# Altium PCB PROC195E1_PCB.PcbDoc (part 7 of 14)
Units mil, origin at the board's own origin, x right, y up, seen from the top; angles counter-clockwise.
Board outline 3110.24 x 2500 mil, 10 copper layers (Top Layer, L02_GND1, L03_SIG1, L04_GND2, L05_PWR1, L06_PWR2, L07_GND3, L08_SIG2, L09_GND4, Bottom Layer), stack 66.407 mil thick; 571 components, 538 nets, 6726 pads, 1286 vias.
Unrouted connection lines stored in the file: 4.
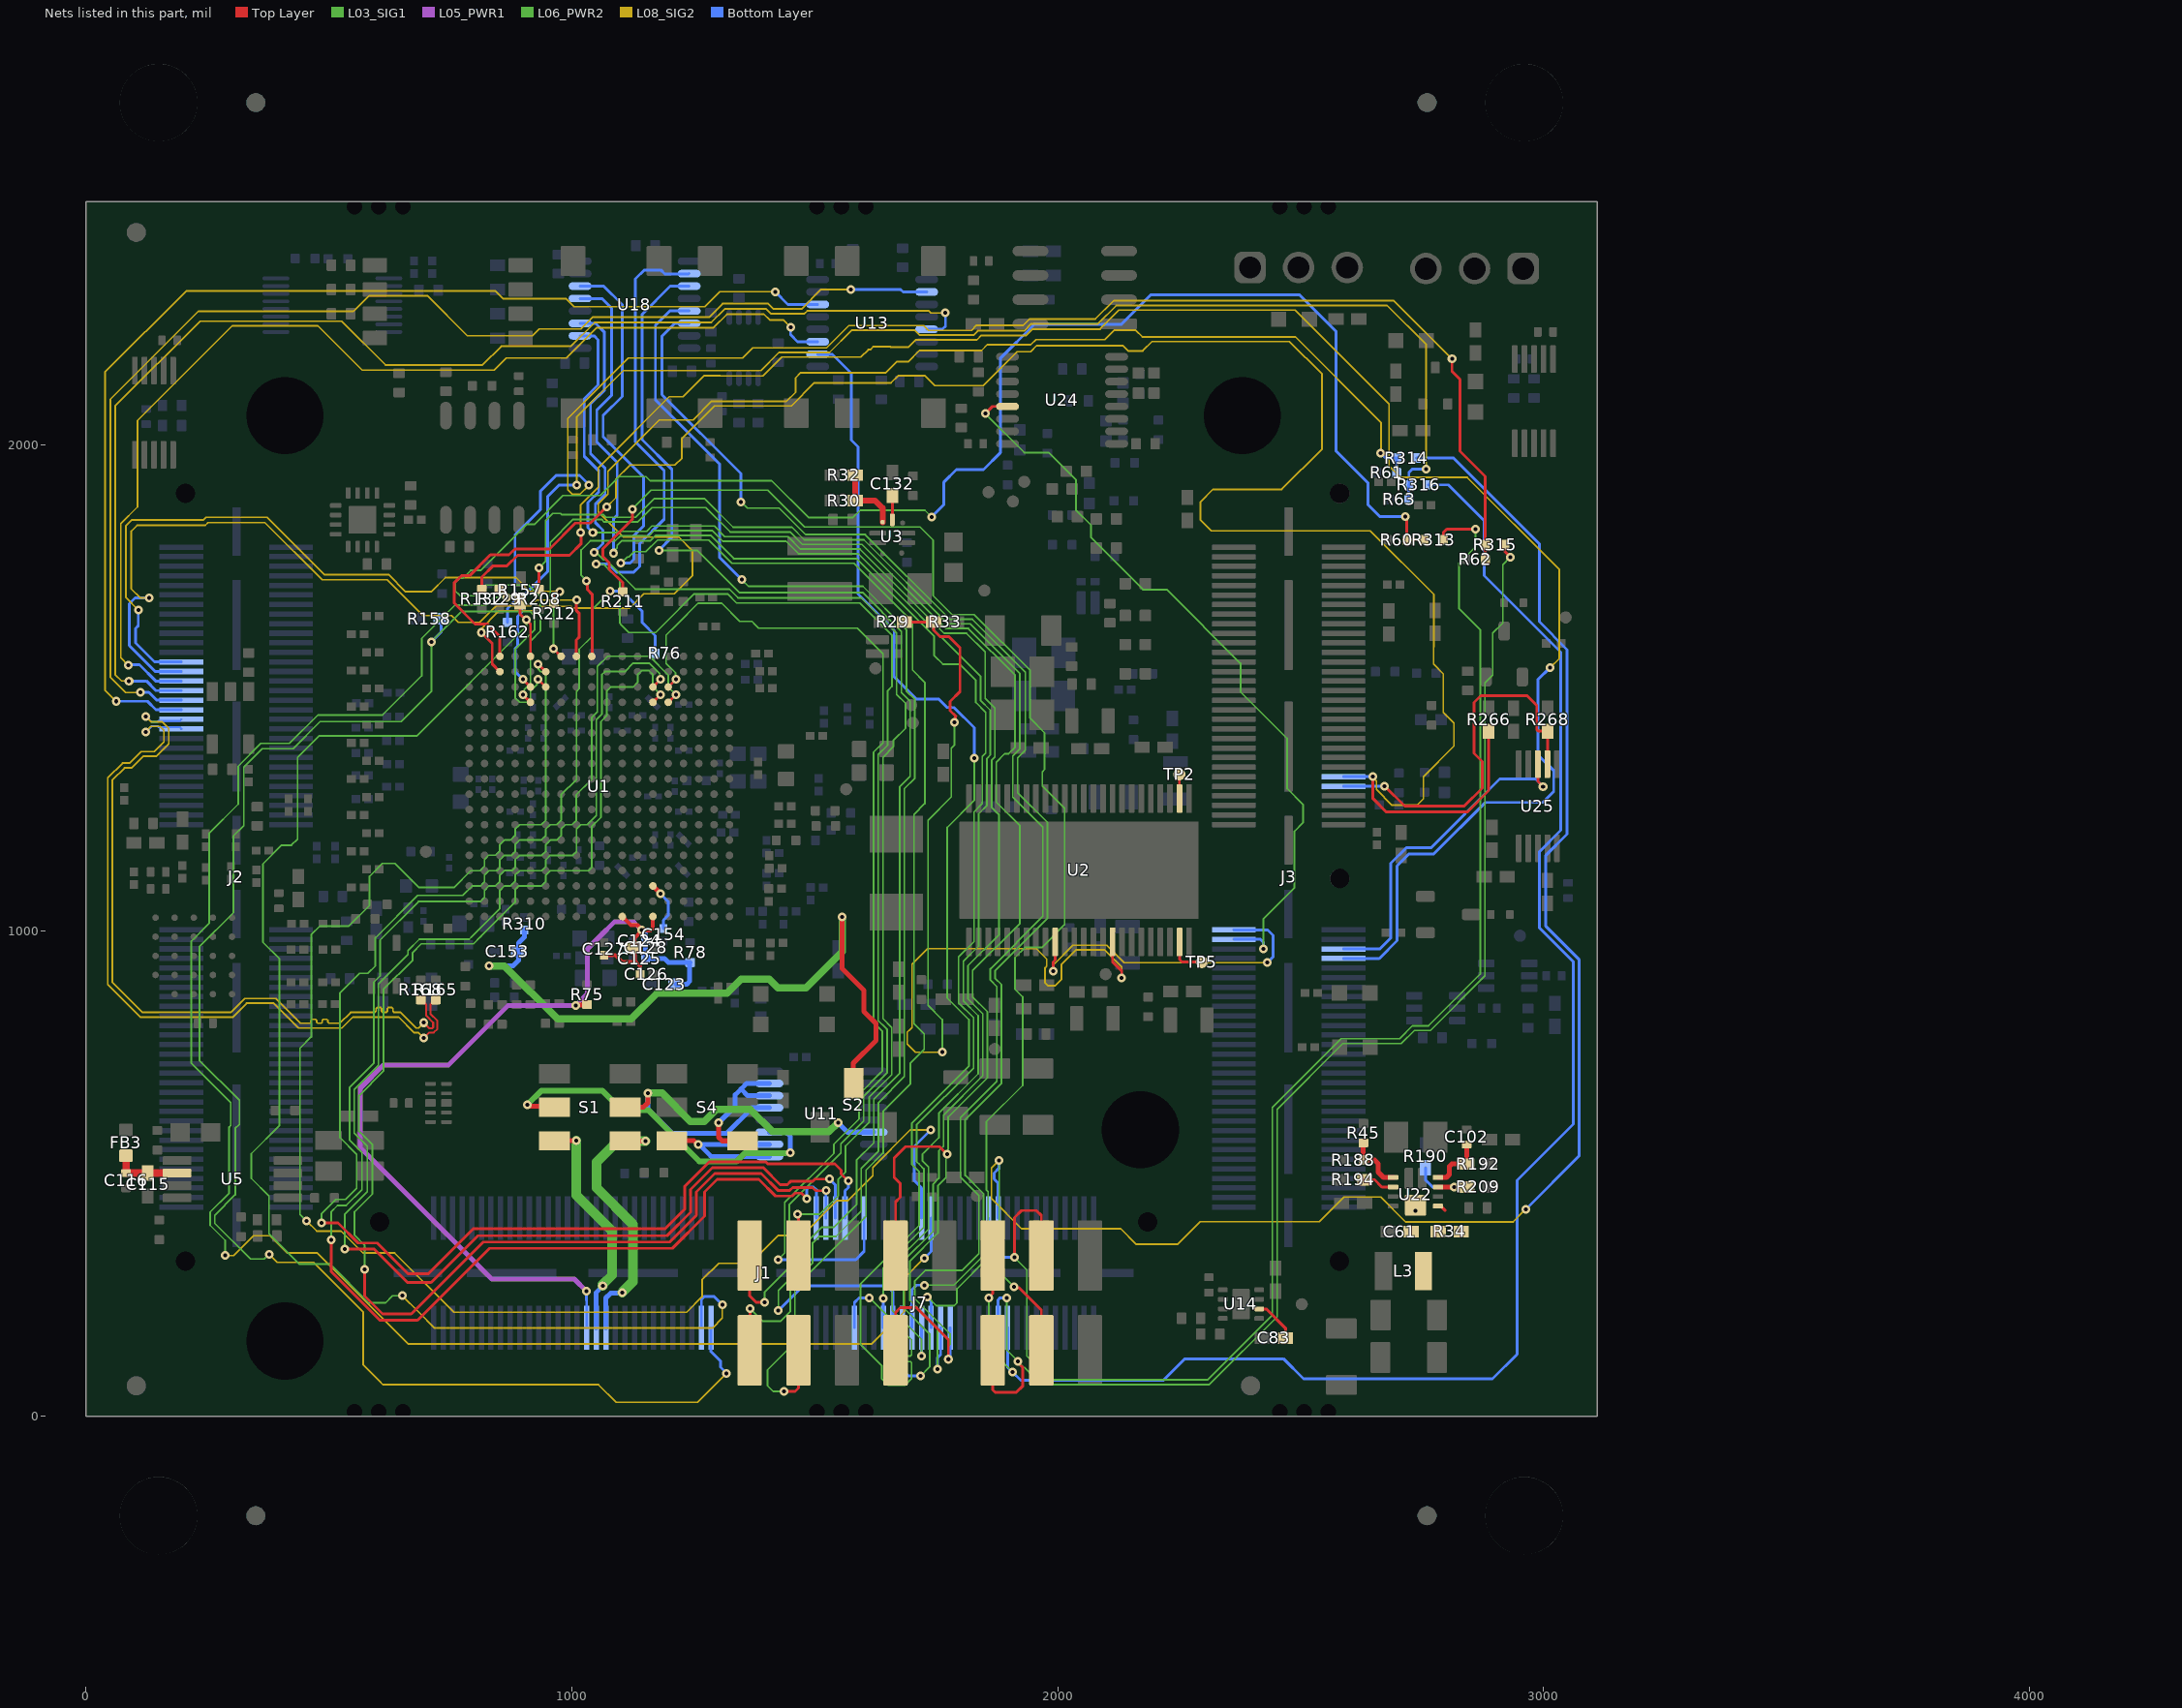
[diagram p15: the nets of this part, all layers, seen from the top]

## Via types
v1: diameter 18, hole 8, Top Layer to Bottom Layer, tented both sides, 1226 vias
v2: diameter 19.68, hole 7.87, Top Layer to Bottom Layer, tented top, 54 vias
v3: diameter 19.68, hole 7.87, Top Layer to Bottom Layer, 4 vias
v4: diameter 19.68, hole 7.87, Top Layer to Bottom Layer, tented both sides, 2 vias

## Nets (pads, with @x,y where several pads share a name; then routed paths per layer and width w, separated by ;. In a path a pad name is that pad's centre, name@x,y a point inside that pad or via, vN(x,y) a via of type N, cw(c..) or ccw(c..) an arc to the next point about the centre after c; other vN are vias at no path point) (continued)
AM26x_FSITX0_DATA1: J1.51 U13.10 | length 2838.3
  L03_SIG1 w3.6: v1(1611.93,244.13) 1612.5,244.13 1699.43,157.2 1699.43,140.08 1699.43,126.68 1697.11,124.36 1690.19,124.36 1687.87,122.04 1687.87,115.08 1690.19,112.76 1697.11,112.76 1699.43,110.44 1699.43,89.65 1699.43,77.7 1685.98,64.25 1651.49,64.25 1638,77.73 1638,104.7 1594.01,148.69 1594.01,272.33 1715.04,393.35 1715.04,503.38 1700.16,518.26 1700.16,603.85 1817.25,720.94 1817.25,816.87 1772.63,861.5 1772.63,1212.37 1828.23,1267.97 1828.23,1355.33 v1(1828.18,1355.38)
  Bottom Layer w5.8: U13.10@1506.16,2186.48 1506.44,2186.2 1536.6,2186.2 1575.47,2147.33 1575.47,2009.53 1589.1,1995.91 1589.1,1692.69 1663.6,1618.19 1663.6,1522.41 1709.38,1476.62 1755.38,1476.62 1772.91,1459.09 1786.71,1459.09 1828.23,1417.58 v1(1828.18,1355.38) v1(1828.18,1355.38) ; J1.51@1581.89,182.81 1581.89,234.28 1591.5,243.88 1611.68,243.88 v1(1611.93,244.13)
AM26x_GPIO15: J3.57 U24.13 | length 1593.9
  Top Layer w5.6: v1(1850.98,2064.05) 1865.76,2078.83 U24.13@1896.89,2078.83
  L03_SIG1 w3.6: v1(1850.98,2064.05) 1931.02,1984 1981.42,1984 2038,1927.42 2038,1865 2068.76,1834.24 2068.76,1808.75 2175.51,1702 2224.36,1702 2376.36,1550.01 2376.36,1491.55 2472.23,1395.67 2472.23,1292.44 2504.98,1259.7 2504.98,1222.01 2487.43,1204.46 2487.43,1088.43 2423.59,1024.59 v1(2423.59,962.08)
  Bottom Layer w5.8: J3.57@2362.59,981.95 2417.29,981.95 2423.59,975.65 v1(2423.59,962.08)
AM26x_I2C1_SCL: J3.70 R268.1 U25.2 | length 785.1
  Top Layer w5.8: v1(2672.84,1297.32) 2714.05,1256.11 2836.5,1256.11 2873.74,1293.35 2873.74,1348.26 2857,1365 2857,1469.5 2870.83,1483.33 2966.1,1483.33 2985.82,1463.61 2985.82,1413.75 2989.22,1410.36 R268.1@3008.15,1410.36 ; U25.2@3007.89,1342.68 R268.1@3007.89,1410.1
  Bottom Layer w5.8: J3.70@2588.19,1297.03 2588.28,1296.94 2672.46,1296.94 v1(2672.84,1297.32)
AM26x_I2C1_SDA: J3.72 R266.1 U1.A3 | length 4431.8
  Top Layer w5.8: U1.A3@852.16,1564.41 852.16,1593.93 852.16,1605.61 826.62,1631.15 801.26,1631.15 757.85,1674.56 757.85,1715.18 772.93,1730.26 789.46,1730.26 832.64,1773.44 871.04,1773.44 883.15,1785.55 954.32,1785.55 1007.6,1838.83 1038.07,1838.83 1070.96,1871.72 v1(1071.74,1871.72) ; v1(2648.87,1316.77) 2648.87,1271.7 2676.61,1243.96 2842.74,1243.96 2886.74,1287.97 R266.1@2886.74,1410.44
  L08_SIG2 w3.6: v1(1071.74,1871.72) 1091.15,1891.12 1091.15,1929.04 1120.44,1958.33 1212.42,1958.33 1226.68,1972.59 1226.68,2012.87 1293.77,2079.97 1452.08,2079.97 1499.47,2127.35 1657.05,2127.35 1671.78,2142.07 1727.43,2142.07 1747.63,2121.87 1846.69,2121.87 1916.37,2191.55 1944.5,2191.55 1957.04,2204.09 2134.12,2204.09 2145,2193.22 2175.1,2193.22 2194.15,2212.27 2477.09,2212.27 2544.06,2145.31 2544.06,1991.06 2461.15,1908.15 2443.18,1908.15 2442.98,1907.95 2319.32,1907.95 2294.01,1882.64 2294.01,1844.62 2315.85,1822.78 2643.4,1822.78 2774.18,1692 2774.18,1584.05 2773.5,1583.37 2773.5,1548.49 2793.6,1528.38 2793.6,1449.18 2815.54,1427.24 2815.54,1379.84 2752.53,1316.83 2752.53,1271.29 2739.3,1258.06 2688.34,1258.06 2656.04,1290.36 2656.04,1307.46 2648.87,1314.63 v1(2648.87,1316.77)
  Bottom Layer w5.8: J3.72@2588.19,1316.71 v1@2648.84,1316.74
AM26x_I2C2_SCL: J1.61 R158.1 U1.C6 | length 3583.7
  Top Layer w5.8: v1(930.9,1517.16) U1.C6@946.64,1501.41
  L03_SIG1 w3.6: v1(377.18,334) 376.76,334 366.79,324.03 338.89,324.03 265.63,397.28 265.63,414.12 307.74,456.23 307.74,593 316.24,601.51 316.24,650.76 234,733 234,967 303.91,1036.91 303.91,1194.87 325.25,1216.2 325.25,1336.36 363.27,1374.39 426.53,1374.39 482.28,1430.15 649.46,1430.15 711.12,1491.81 v1(711.12,1594.47) 773.76,1657.1 914.26,1657.1 923.55,1647.81 923.55,1618.52 883.7,1578.67 883.7,1479.16 892.94,1469.92 908.34,1469.92 915.17,1476.76 915.17,1493.16 928.79,1506.77 928.79,1514.64 v1@930.9,1516.75
  L08_SIG2 w3.6: v1(377.18,334) 394.11,317.08 468.4,317.08 571,214.48 571,106 604,73 611.5,65.5 1055.12,65.5 1091.64,28.98 1258.77,28.98 v1(1318.55,88.75)
  Bottom Layer w5.8: v1(711.12,1594.47) 730.98,1614.32 R158.1@730.98,1641.8 ; J1.61@1286.71,182.59 1286.71,133.41 1306.18,113.95 1306.18,101.12 v1(1318.55,88.75)
AM26x_I2C2_SDA: J1.63 R157.1 U1.A5 | length 2963.9
  Top Layer w5.66: U1.A5@915.15,1564.41 915.15,1597.28
  Top Layer w5.8: R157.1@893.54,1676.28 893.54,1651.6 905.46,1639.68 v1(906.7,1639.68) ; v1@907.19,1639.68 907.19,1638.66 915.15,1630.71 915.15,1597.28
  L03_SIG1 w3.6: v1(651.34,248.48) 631.52,248.48 616.97,233.92 582.36,233.92 502.39,313.9 439.13,313.9 377.16,375.87 377.16,453.53 340.65,490.04 340.65,540.87 398.64,598.85 398.64,941.93 364.71,975.87 364.71,1137.23 403.3,1175.82 423.23,1175.82 435.79,1188.38 435.79,1356.41 480.07,1400.68 680.91,1400.68 906.7,1626.47 v1(906.7,1639.68)
  L08_SIG2 w3.6: v1(651.34,248.48) 684.89,214.93 717.89,181.93 1289.54,181.93 1309.9,202.29 v1(1309.9,229.66)
  Bottom Layer w5.8: J1.63@1267.03,182.59 1267.03,241.09 1272.46,246.53 1293.31,246.53 1309.9,229.93 v1(1309.9,229.66)
AM26x_LIN1_RXD: J1.37 U1.A9 | length 2800.2
  Top Layer w5.8: v1(1030.57,1720.11) 1032.02,1718.67 1032.02,1702.07 1041.9,1692.19 1041.9,1565.18 U1.A9@1041.13,1564.41
  L03_SIG1 w3.6: v1(1030.57,1720.11) 1019.47,1731.21 1019.47,1783.38 1038.49,1802.4 1089.57,1802.4 1099.4,1812.23 1157.93,1812.23 1168.8,1823.1 1289.49,1823.1 1311.16,1801.42 1440.97,1801.42 1466.78,1775.61 1589.29,1775.61 1841.23,1523.67 1841.23,1473.7 1861.33,1453.6 1861.33,1361.33 1854.62,1354.62 1854.62,1257.62 1837.4,1240.4 1837.4,968.4 1805.86,936.86 1805.86,855.42 1836.45,824.83 1836.45,705.3 1755.49,624.34 1755.49,573.71 1727.03,545.25 1724.49,542.72 1721.89,540.11 1721.89,526.19 1724.49,523.59 1734.24,513.84 1734.24,385.4 1659.74,310.9 1659.74,218.82 1719.9,158.66 v1(1719.9,124.59)
  Bottom Layer w5.8: v1(1719.9,124.59) J1.37@1719.9,182.59
AM26x_LIN1_TXD: J1.35 R211.1 | length 2868.2
  Top Layer w5.8: R211.1@1105.33,1697.05 1105.33,1715.64 1077.2,1743.77 1077.2,1756.98 1064.22,1769.95 1064.22,1785.99 1124.75,1846.52 v1(1124.75,1867.56)
  L03_SIG1 w3.6: v1(1124.75,1867.56) 1163.69,1906.51 1403.76,1906.51 1479.42,1830.84 1716.79,1830.84 1743.79,1803.84 1743.79,1689.41 1782.68,1650.52 1828.25,1650.52 1943.3,1535.47 1943.3,1437.04 1972.96,1407.38 1972.96,1331.48 1968.45,1326.96 1968.45,1297.89 2014.41,1251.93 2014.41,1012.41 1967.24,965.24 1932.98,965.24 1912.14,944.4 1912.14,879.43 1928.06,863.51 1928.06,681.38 1853.22,606.54 1853.22,466.18 1856.98,462.42 1856.98,327.01 1792.63,262.65 1792.63,233.83 1786.72,227.92 1750.41,227.92 v1(1732.17,246.17)
  Bottom Layer w5.8: v1(1732.17,246.17) 1732.17,243.71 1739.59,236.29 J1.35@1739.59,182.59
AM26x_MCAN0_RX: J1.38 U1.B6 | length 3385.6
  Top Layer w5.8: v1(930.9,1548.66) U1.B6@946.64,1532.91 U1.B6@946.33,1532.91
  L03_SIG1 w3.6: v1(454.77,402.13) 441,415.9 441,758 464.2,781.2 464.2,991.36 482.16,1009.33 541.33,1009.33 583.88,1051.88 583.88,1111.59 610.63,1138.34 636.17,1138.34 685.86,1088.65 720.46,1088.65 757.5,1088.65 792.16,1123.32 811.23,1123.32 820.61,1132.71 820.61,1146.61 829.01,1155.01 842.91,1155.01 852.16,1164.25 852.16,1177.16 861.4,1186.41 861.79,1186.41 861.89,1186.5 874.41,1186.5 883.65,1195.75 883.65,1208.66 892.99,1218 937.4,1218 946.6,1227.2 946.6,1527.99 941.73,1532.86 936.42,1532.86 931.78,1537.5 931.78,1547.15 v1@931.57,1547.35
  L08_SIG2 w3.6: v1(454.77,402.13) 475.45,381.45 525.33,381.45 570.25,336.54 635.5,336.54 757.71,214.33 1236.54,214.33 1268.29,246.08 1268.29,281.1 1302.45,315.27 1367.75,315.27 1424.67,372.19 1474.04,372.19 1546.17,444.32 1568.54,444.32 1619.88,495.66 1619.88,512.8 1696.77,589.69 v1(1738.69,589.69)
  Bottom Layer w5.8: J1.38@1719.9,408.19 1719.9,470.42 1704.9,485.43 1704.9,555.9 v1(1738.69,589.69)
AM26x_MCAN0_TX: J1.36 R129.1 | length 3623
  Top Layer w5.8: R129.1@851.09,1702.04 851.59,1702.04 865.47,1688.16 v1(865.47,1685.82)
  L03_SIG1 w3.6: v1(286.9,331.23) 286.9,362.43 256.03,393.31 256.03,420.71 295.03,459.71 295.03,595.56 298.56,599.1 298.56,645.55 217.33,726.78 217.33,978.29 253.81,1014.77 253.81,1200.34 313.83,1260.35 313.83,1338.52 360.49,1385.19 419.29,1385.19 477.78,1443.68 610.56,1443.68 691.27,1524.39 691.27,1601.15 760.17,1670.05 823.64,1670.05 839.41,1685.82 v1(865.47,1685.82)
  L08_SIG2 w3.6: v1(286.9,331.23) 304.35,331.23 344.89,371.76 379.18,371.76 414.17,336.77 475.86,336.77 663.1,149.53 1617.61,149.53 1683.91,215.83 1683.91,284.16 v1(1725.47,325.72)
  Bottom Layer w5.8: v1(1725.47,325.72) 1739.59,339.84 J1.36@1739.59,408.19
AM26x_MCAN1_RX: J3.56 U25.3 | length 702.6
  Top Layer w5.8: U25.3@2988.2,1342.68 2988.2,1307.23 2998.81,1296.62 v1(2998.81,1296.43)
  Bottom Layer w5.8: J3.56@2588.19,962.26 2663.15,962.26 2685.67,984.78 2685.67,1138.5 2718.16,1171 2768.97,1171 2909.91,1311.94 2983.3,1311.94 v1(2998.81,1296.43)
AM26x_MCAN1_TX: J3.54 R132.1 | length 3992.6
  Top Layer w5.8: R132.1@815.09,1702.04 815.09,1727.52 838.44,1750.87 866.86,1750.87 888.54,1772.55 995.24,1772.55 1019.63,1796.94 1019.63,1818.28 v1(1018.71,1819.2)
  L08_SIG2 w3.6: v1(1018.71,1819.2) 1018.18,1819.73 1018.18,1875.82 1054.51,1912.15 1054.51,1952.55 1200.68,2098.73 1229.1,2098.73 1272.26,2141.89 1305.58,2141.89 1305.74,2141.73 1393.63,2141.73 1432.26,2180.36 1594.98,2180.36 1610.47,2195.84 1614.33,2195.84 1620.17,2201.68 1655.83,2201.68 1656.82,2200.69 1692.48,2200.69 1707.4,2215.62 1833.5,2215.62 1843,2225.12 1935.52,2225.12 1948.52,2238.11 2087.24,2238.11 2126.26,2277.13 2488.34,2277.13 2681.85,2083.61 2681.85,1994.01 2682.03,1993.83 2682.03,1956.63 2705.75,1932.91 2842.75,1932.91 3032.35,1743.31 3032.35,1560.19 3013.91,1541.75 v1(3013.59,1541.75)
  Bottom Layer w5.8: J3.54@2588.19,942.58 2661.85,942.58 2698.67,979.4 2698.67,1133.12 2723.55,1158 2774.36,1158 2880.19,1263.83 2998.09,1263.83 3020.67,1286.41 3020.67,1329.51 2988,1362.18 2988,1516.16 v1(3013.59,1541.75)
AM26x_SDFM0_CLK0: J1.54 R76.1 | length 3243
  Top Layer w5.8: v1(485.49,398.25) 519.02,398.25 560.3,356.97 600.07,356.97 663.13,293.9 705.07,293.9 797.17,386 1191.81,386 1232.91,427.1 1232.91,473.93 1282.53,523.55 1400.02,523.55 1403.53,520.04 1541.39,520.04 1554.17,507.25 1554.17,499.07 1568.18,485.05 v1(1569.29,485.05)
  L03_SIG1 w3.6: v1(485.49,398.25) 485.49,417.46 514.66,446.63 534.66,446.63 557.64,469.61 557.64,539.25 523.21,573.68 523.21,871.76 563.45,912 580.67,912 596.12,927.46 596.12,985.2 683.21,1072.29 720.46,1072.29 775.57,1072.29 795.24,1091.96 812.33,1091.96 820.71,1100.33 820.71,1114.22 829.9,1123.41 846.49,1123.41 852.14,1129.07 852.14,1145.65 861.4,1154.91 875.95,1154.91 883.53,1162.5 883.53,1164.13 883.6,1164.2 883.6,1177.11 892.99,1186.5 937.5,1186.5 945.81,1194.82 945.81,1194.92 946.6,1195.7 946.6,1208.61 955.89,1217.9 968.8,1217.9 978.19,1227.29 978.19,1271.7 978.27,1271.78 978.27,1279.45 1009.68,1310.87 1009.68,1492.17 1015.41,1497.89 1015.41,1579.21 1042.34,1606.13 1042.34,1661.52 v1(1079.48,1698.67)
  Bottom Layer w5.8: v1(1079.48,1698.67) 1103.68,1698.67 1145.19,1657.17 1145.19,1633.71 1171.53,1607.36 R76.1@1171.53,1570.78 ; J1.54@1562.42,408.19 1562.42,464.42 1569.29,471.29 v1(1569.29,485.05)
AM26x_SDFM0_D0: J1.60 U1.D14 | length 3169.4
  Top Layer w5.8: v1(505.01,363.58) 505.01,298.17 605.32,197.86 682.86,197.86 831,346 1206.97,346 1273.33,412.36 1273.33,461.99 1299.48,488.15 1384.89,488.15 1419.33,453.7 1453.71,453.7 1459.55,459.54 1472.46,459.54 v1(1483.64,448.37) ; U1.D14@1198.61,1469.92 v1(1214.36,1485.67)
  L03_SIG1 w3.6: v1(505.01,363.58) 505.01,421.1 518.13,434.21 535.82,434.21 568.44,466.83 568.44,543.72 542.83,569.33 542.83,676.84 592.67,726.67 592.67,893.64 605.72,906.69 605.72,980.84 684.59,1059.71 812.02,1059.71 820.71,1068.4 820.71,1082.72 829.91,1091.92 841.38,1091.92 841.48,1092.01 842.91,1092.01 852.11,1101.21 852.11,1102.65 852.21,1102.74 852.21,1114.22 861.5,1123.51 874.41,1123.51 874.46,1123.56 877.62,1123.56 883.7,1129.64 883.7,1145.71 892.95,1154.96 938.4,1154.96 946.69,1163.25 946.69,1177.21 955.89,1186.41 969.11,1186.41 978.19,1195.49 978.19,1208.71 987.43,1217.95 1000.34,1217.95 1009.59,1227.2 1009.59,1271.7 1009.23,1272.06 1009.23,1279.23 1040.99,1310.99 1040.99,1438.07 1052.86,1449.95 1052.86,1543.44 1074.06,1564.64 1160.05,1564.64 1198.76,1525.93 1198.76,1501.27 v1(1214.36,1485.67)
  Bottom Layer w5.8: v1(1483.64,448.37) 1483.64,466.9 1489.05,472.31 1497.65,472.31 1503.37,466.6 J1.60@1503.37,408.19
AM26x_SDFM0_D1: J1.58 U1.D13 | length 3012.8
  Top Layer w5.8: v1(573.98,302.27) 573.98,247.59 610.7,210.86 669.86,210.86 818,359 1201.58,359 1256.51,413.93 1256.51,461.86 1294.6,499.95 1389.77,499.95 1424.22,465.5 1448.82,465.5 1454.66,471.34 1495.52,471.34 1502.34,464.53 v1@1522.88,464.53 ; U1.D13@1167.12,1469.92 v1(1182.87,1485.67)
  L03_SIG1 w3.6: v1(573.98,302.27) 573.98,352.27 553.07,373.18 553.07,421.22 590.04,458.2 590.04,559.37 565.2,584.21 562.03,587.38 562.03,660.33 612.64,710.93 612.64,879.06 672.79,939.21 672.79,955.01 690.47,972.69 798.11,972.69 812.76,987.34 883.5,1058.09 883.5,1084.56 890.96,1092.01 937.4,1092.01 938.75,1093.37 938.98,1093.37 946.69,1101.08 946.69,1114.22 955.89,1123.41 1035.15,1123.41 1041.09,1129.35 1041.09,1213.76 1060.19,1232.86 1060.19,1430.12 1072.06,1442 1072.06,1493.28 1080.24,1501.46 1126.23,1501.46 1135.77,1511 1135.77,1527.06 1144.08,1535.37 1158.8,1535.37 1167,1527.17 1167,1501.53 1182.56,1485.97 v1@1182.56,1485.67
  Bottom Layer w5.8: J1.58@1523.05,408.19 v1@1523.08,464.72
  other v1: 1523.11,464.75
AM26x_SDFM0_D2: J1.56 U1.C13 | length 2980.4
  Top Layer w5.8: v1(533.25,344.85) 592.92,344.85 662.01,275.77 710.77,275.77 807,372 1196.2,372 1244.71,420.51 1244.71,467.34 1289.12,511.75 1394.66,511.75 1429.11,477.3 1443.94,477.3 1450.28,483.65 1495.46,483.65 1500.41,488.6 v1(1530.62,488.6) ; U1.C13@1167.12,1501.41 v1(1182.87,1517.16)
  L03_SIG1 w3.6: v1(533.25,344.85) 533.25,416.68 579.24,462.67 579.24,556.59 552.43,583.4 552.43,672.86 602.49,722.92 602.49,889.88 663.19,950.58 663.19,958.98 686.5,982.29 789.21,982.29 794.26,987.34 852.11,1045.19 852.11,1082.62 861.4,1091.92 865.82,1091.92 865.91,1092.02 874.41,1092.02 883.6,1101.21 883.6,1113.98 892.94,1123.31 938.25,1123.31 946.69,1131.76 946.69,1145.71 955.89,1154.91 1002.27,1154.91 1009.69,1162.33 1009.69,1208.71 1019.08,1218.1 1031.85,1218.1 1050.59,1236.84 1050.59,1434.1 1062.46,1445.97 1062.46,1527.31 1068.29,1533.14 1109.11,1533.14 1126.5,1550.54 1159.58,1550.54 1181.33,1528.79 1181.33,1518.7 v1(1182.87,1517.16)
  Bottom Layer w5.8: v1(1530.62,488.6) 1542.74,476.48 J1.56@1542.74,408.19
AM26x_SDFM0_D3: J1.50 U1.C14 | length 2243.6
  Top Layer w5.8: U1.C14@1198.61,1501.41 v1(1214.36,1517.16)
  L03_SIG1 w3.6: v1@1213.68,1515.86 1213.68,1530.52 1194.28,1549.92 1194.28,1608.12 1215.81,1629.65 1260.03,1673.86 1308.57,1673.86 1345.92,1636.51 1371.03,1636.51 1377.9,1629.65 1384.89,1622.65 1390.29,1622.65 1588.11,1622.65 1640.67,1570.09 1640.67,1386.52 1621.24,1367.09 1621.24,810.88 1637.01,795.11 1639.35,792.77 1639.35,711.27 1637.01,708.92 1591.28,663.19 1591.28,612.28 1539.43,560.43 1539.43,541.5 1438.27,440.33 1438.27,336.62 v1(1424.49,322.85)
  Bottom Layer w5.8: v1(1424.49,322.85) 1584.72,322.85 1601.79,339.92 J1.50@1601.79,408.19
AM26x_SPI0_CLK: J2.34 U13.2 | length 2591.3
  L08_SIG2 w3.6: v1(112.11,1490.15) 82.04,1490.15 50.46,1521.73 50.46,2093.36 232.06,2274.96 551.56,2274.96 583.47,2306.87 702.63,2306.87 785.11,2224.39 919.15,2224.39 933.02,2238.26 1018.48,2238.26 1042.84,2262.61 1282.72,2262.61 1310.49,2290.39 1404.54,2290.39 1415.43,2279.49 1472.87,2279.49 1513.19,2319.81 v1(1574.52,2319.81)
  Bottom Layer w5.8: v1(112.11,1490.15) 112.36,1490.4 129.78,1490.4 145.9,1474.27 J2.34@196.81,1474.27 ; v1(1574.52,2319.81) 1676.43,2319.81 1681.8,2314.43 U13.2@1730.57,2314.43
AM26x_SPI0_CS0: J2.36 U13.14 | length 2400.7
  L08_SIG2 w3.6: v1(62.59,1472.04) 39.66,1494.98 39.66,2149.3 206.82,2316.47 843.62,2316.47 859.75,2300.34 988.89,2300.34 1005.02,2284.21 1273.77,2284.21 1304.55,2314.99 v1(1418.58,2314.99)
  Bottom Layer w5.8: v1(62.59,1472.04) 127.02,1472.04 144.47,1454.59 J2.36@196.81,1454.59 ; v1@1418.76,2314.99 1444.91,2288.84 U13.14@1506.16,2288.84
AM26x_SPI0_D0: J2.32 U13.5 | length 2645.4
  L08_SIG2 w3.6: v1(89.1,1513.74) 73.72,1513.74 60.5,1526.96 60.5,2079.58 235.37,2254.46 526.54,2254.46 616.69,2164.31 816.67,2164.31 855.1,2202.74 998.23,2202.74 1047.31,2251.81 1287.19,2251.81 1314.96,2279.59 1400.07,2279.59 1409.76,2269.89 1479.01,2269.89 1484.74,2275.62 1735.1,2275.62 1739.44,2271.28 v1(1769.11,2271.28)
  Bottom Layer w5.8: v1(89.1,1513.74) 124.82,1513.74 144.6,1493.96 J2.32@196.81,1493.96 ; U13.5@1730.57,2237.66 1762.88,2237.66 1769.11,2243.89 v1(1769.11,2271.28)
AM26x_SPI0_D1: J2.30 U13.11 | length 2246.4
  L08_SIG2 w3.6: v1(87.54,1546.2) 72.06,1561.68 72.06,1837.67 106.54,1872.15 106.54,2050 301.4,2244.86 477.81,2244.86 568.96,2153.71 840.62,2153.71 865.48,2178.58 989.34,2178.58 1051.78,2241.01 1291.66,2241.01 1319.44,2268.79 1395.59,2268.79 1407.34,2257.04 1435.18,2257.04 v1(1450.35,2241.87)
  Bottom Layer w5.8: v1(87.54,1546.2) 88.51,1547.17 110.66,1547.17 143.91,1513.92 143.91,1513.64 J2.30@196.81,1513.64 ; v1(1450.35,2241.87) 1450.35,2226.69 1464.96,2212.07 U13.11@1506.16,2212.07
AM26x_SPI3_CLK: J1.41 U18.2 | length 3168.8
  L03_SIG1 w3.6: v1(1043.71,1819.2) 1092.79,1819.2 1095.42,1821.83 1153.95,1821.83 1164.82,1832.7 1293.46,1832.7 1315.14,1811.02 1444.94,1811.02 1470.75,1785.21 1593.26,1785.21 1766.35,1612.12 1812.34,1612.12 1850.83,1573.64 1850.83,1478.14 1870.93,1458.04 1870.93,1357.35 1864.22,1350.64 1864.22,1253.93 1879,1239.15 1879,991.12 1815.46,927.58 1815.46,859.39 1846.05,828.8 1846.05,701.33 1765.09,620.36 1765.09,556.49 1755.49,546.89 1755.49,490.24 1743.84,478.59 1743.84,381.42 1682.73,320.31 1682.73,223.9 1736.7,169.93 1736.7,101.97 v1(1718.12,83.39)
  Bottom Layer w5.8: U18.2@1017.3,2224.24 1046.28,2224.24 1054.46,2216.06 1054.46,2123.22 1025.75,2094.5 1025.75,1976.33 1055.68,1946.4 1055.68,1903.1 1033.44,1880.87 1033.44,1829.47 v1(1043.71,1819.2) ; J1.41@1680.53,182.59 1680.53,95.92 1693.06,83.39 v1(1718.12,83.39)
AM26x_SPI3_CS0: J1.39 U18.14 | length 2790.3
  L03_SIG1 w3.6: v1(1347.95,1882.51) 1348.64,1882.51 1361.35,1869.79 1426.9,1869.79 1481.66,1815.03 1604.17,1815.03 1778.28,1640.92 1824.27,1640.92 1933.7,1531.49 1933.7,1371.4 1917.47,1355.16 1917.47,1284.09 1979.19,1222.37 1979.19,1174.98 1979.13,1174.92 1979.13,1108.06 1979.13,1025.28 1871.08,917.24 1871.08,902.02 1884.45,888.65 1884.45,685.42 1809.74,610.71 1809.74,496.09 1847.38,458.45 1847.38,330.99 1786.65,270.25 v1(1725.47,270.25)
  Bottom Layer w5.8: U18.14@1241.71,2249.84 1212.07,2249.84 1185.71,2223.47 1185.71,2102.96 1347.95,1940.72 v1(1347.95,1882.51) ; J1.39@1700.22,182.59 1700.22,260.81 1709.66,270.25 v1(1725.47,270.25)
AM26x_SPI3_D0: J1.45 U18.5 | length 2987.3
  L03_SIG1 w3.6: v1(1086.43,1776.94) 1086.43,1780.83 1093.53,1787.93 1093.53,1792.78 1103.37,1802.63 1161.91,1802.63 1172.78,1813.5 1285.51,1813.5 1333.32,1765.69 1585.63,1765.69 1745.98,1605.34 1745.98,1566.11 1763.64,1548.45 1797.9,1548.45 1831.63,1514.73 1831.63,1469.5 1851.73,1449.4 1851.73,1365.3 1844.98,1358.55 1844.98,1261.55 1827.8,1244.37 1827.8,977.31 1796.26,945.78 1796.26,851.44 1826.85,820.85 1826.85,716.96 1709.76,599.87 1709.76,524.74 1714.89,519.61 1724.64,509.86 1724.64,389.38 1641.16,305.9 v1(1641.16,242.69)
  Bottom Layer w5.8: U18.5@1017.3,2301.02 1061.89,2301.02 1081.91,2281 1081.91,2101.67 1051.75,2071.51 1051.75,2005.84 1093.61,1963.98 1093.61,1855.35 1086.43,1848.17 v1(1086.43,1776.94) ; J1.45@1641.16,182.59 v1(1641.16,242.69)
AM26x_SPI3_D1: J1.43 U18.11 | length 3078.8
  L03_SIG1 w3.6: v1(1180.12,1782.71) 1258.08,1782.71 1344.93,1695.86 1598.55,1695.86 1678.64,1615.77 1678.64,1489.7 1696.6,1471.74 1696.6,1317.75 1674.87,1296.02 1674.87,706.05 1621.66,652.85 1621.66,562.75 1586.09,527.18 1586.09,435.92 1539.35,389.18 1513.97,389.18 1486.14,361.36 1486.14,320.5 1425.26,259.61 v1(1425.26,218.01)
  Bottom Layer w5.8: v1(1180.12,1782.71) 1180.12,1783.67 1206.18,1809.73 1206.18,1949.45 1144.69,2010.93 1144.69,2268.37 1202.93,2326.61 U18.11@1241.71,2326.61 ; v1(1425.26,218.01) 1476.11,268.86 1648.36,268.86 1660.85,256.37 J1.43@1660.85,182.59
AM26x_TCK: R61.1 R314.2 U1.B3 | length 2895.6
  Top Layer w5.66: 836.41,1548.66 836.41,1591.31
  Top Layer w5.8: v1(814.18,1613.54) 836.41,1591.31 ; 836.41,1548.66 U1.B3@852.16,1532.91
  L08_SIG2 w3.6: v1(814.18,1613.54) 814.19,1621.89 846.57,1654.27 846.88,1654.27 850.84,1658.22 920.6,1658.22 929.85,1667.47 999.16,1667.47 1003.02,1663.61 1119.01,1663.61 1148.63,1693.23 1211.25,1693.23 1248.28,1730.26 1248.28,1782.12 1220.57,1809.84 1106.58,1809.84 1054.61,1861.81 1054.61,1878.73 1074.52,1898.64 1074.52,1945.42 1180.23,2051.12 1249.65,2051.12 1288.1,2089.57 1442.35,2089.57 1460.72,2107.93 1460.72,2137.48 1471.6,2148.37 1646.35,2148.37 1668.87,2170.89 1692.57,2170.89 1715.7,2194.02 1843.35,2194.02 1855.25,2205.92 1944.68,2205.92 1955.27,2216.51 2096.77,2216.51 2115.91,2235.66 2160.69,2235.66 2174.48,2221.87 2489.43,2221.87 2665.23,2046.07 2665.23,1983.61 v1(2664.5,1982.88)
  Bottom Layer w5.8: v1(2664.5,1982.88) 2674.83,1972.55 R314.2@2698.04,1972.55 2697.55,1972.06 2697.55,1969.54 R61.1@2697.55,1942.55
AM26x_TDI: R63.1 R316.2 U1.C5 | length 2876.5
  Top Layer w5.8: v1(899.4,1517.16) U1.C5@915.15,1501.41
  L08_SIG2 w3.6: v1(1010.08,1917.36) 1010.08,2056.72 1106.05,2152.69 1389.31,2152.69 1426.58,2189.96 1530.45,2189.96 1576.23,2235.74 1706.53,2235.74 1716.59,2225.68 1826.6,2225.68 1835.63,2234.72 1931.55,2234.72 1945.74,2248.91 2082.77,2248.91 2120.58,2286.73 2677.71,2286.73 2758.3,2206.14 v1(2758.3,1950.23)
  Bottom Layer w5.8: v1(899.4,1517.16) 884.1,1532.46 884.1,1580.99 888.8,1585.69 888.8,1629.65 888.8,1647.09 896.37,1654.66 896.37,1684.79 950.93,1739.36 950.93,1893.84 974.45,1917.36 v1(1010.08,1917.36) ; R63.1@2722.66,1887.37 R316.2@2722.66,1917.46 2722.86,1917.66 2722.86,1943.02 2730.06,1950.23 v1(2758.3,1950.23)
AM26x_TDO: R62.1 R162.1 R315.2 | length 3040.6
  Top Layer w5.8: v1(2811.5,2176.74) 2811.5,2151.17 2828.11,2134.56 2828.11,1986.89 2879.97,1935.03 R315.2@2879.97,1794.32 R62.1@2879.97,1764.32
  L08_SIG2 w3.6: v1(1035.48,1916.88) 1016.39,1897.79 1001.72,1897.79 991.88,1907.63 991.88,2053.79 1116.56,2178.47 1351.69,2178.47 1372.78,2199.56 1524.56,2199.56 1570.35,2245.34 1724.65,2245.34 1734.71,2235.28 1822.62,2235.28 1833.35,2246.01 1929.26,2246.01 1942.26,2259 2077.59,2259 2114.91,2296.33 2691.91,2296.33 v1(2811.5,2176.74)
  Bottom Layer w5.8: R162.1@867.9,1634.36 867.9,1662.95 883.37,1678.41 883.37,1746.47 ; 883.33,1746.5 883.33,1814.56 936,1867.23 936,1904.85 967.82,1936.67 1016.62,1936.67 1035.48,1917.81 v1(1035.48,1916.88)
AM26x_TMS: R60.1 R313.2 U1.D5 | length 3321.1
  Top Layer w5.8: v1(899.4,1485.67) U1.D5@915.15,1469.92 ; v1(2715.5,1851.88) 2715.5,1848.58 2718.53,1845.55 R60.1@2718.53,1804.15 R313.2@2753.53,1804.15
  L03_SIG1 w3.6: v1@899.6,1484.89 902.16,1487.45 902.16,1495.96 915.17,1508.98 915.17,1596 935.55,1616.38 935.55,1629.65 935.55,1687.04 911.35,1711.23 823.63,1711.23 801.74,1689.35 770.41,1689.35 758.95,1700.81 758.95,1714.73 769.3,1725.08 775.84,1725.08 792.1,1741.33 812.39,1741.33 907.14,1836.08 922.79,1836.08 982.3,1895.59 1058.6,1895.59 1097.27,1934.26 1152.86,1934.26 1161.17,1925.95 1411.47,1925.95 1486.99,1850.43 1579.02,1850.43 1593.79,1865.2 1726.83,1865.2 v1(1740.5,1851.54)
  Bottom Layer w5.8: v1(1740.5,1851.54) 1766.07,1877.11 1766.07,1923.25 1791.56,1948.73 1847.25,1948.73 1881.95,1983.44 1881.95,2177.46 1952.18,2247.69 2130.98,2247.69 2191.75,2308.45 2497.79,2308.45 2572.87,2233.37 2572.87,1987.07 2639,1920.93 2639,1876.33 2663.45,1851.88 v1(2715.5,1851.88)
AM26x_UART0_RXD: J1.33 J7.9 U1.A7 | length 3412.6
  Top Layer w5.8: v1(962.39,1580.15) U1.A7@978.14,1564.41 U1.A7@977.83,1564.41 ; J7.9@1666.47,331.06 1666.47,441.85 1675.79,451.17 1675.79,479.56 1663.48,491.88 1663.48,532.03 1686.75,555.31 1756.91,555.31 v1(1772.29,539.93)
  L03_SIG1 w3.6: v1(962.39,1580.15) 962.39,1683.43 956.1,1689.72 956.1,1799.13 1003.29,1846.32 1061.29,1846.32 1066.46,1841.16 1135.68,1841.16 1165.12,1870.6 1276.22,1870.6 1326.21,1820.62 1448.92,1820.62 1474.73,1794.81 1597.24,1794.81 1770.33,1621.72 1816.32,1621.72 1912.44,1525.61 1912.44,1377.37 1898.99,1363.92 1891.08,1363.92 1873.82,1346.66 1873.82,1264.34 1922.26,1215.9 1922.26,1014.87 1825.06,917.67 1825.06,863.37 1855.65,832.78 1855.65,697.35 1774.69,616.38 1774.69,544.6 v1@1771.15,541.06 ; v1(1752.77,97.06) 1752.77,182.23 1696.14,238.86 1696.14,320.14 1753.44,377.45 1753.44,474.62 1770.02,491.2 1770.02,539.93 v1(1772.29,539.93)
  Bottom Layer w5.8: v1(1752.77,97.06) 1752.77,120.79 1759.27,127.29 J1.33@1759.27,182.59
AM26x_UART0_TXD: J1.31 J7.10 R208.1 | length 3293
  Top Layer w5.8: v1(932.72,1746.47) 932.91,1746.28 932.91,1702.23 R208.1@933.1,1702.04 ; J7.10@1666.47,136.18 1666.47,214.29 1676.13,223.95 1709.41,223.95 1775.14,158.23 v1(1775.14,117.85)
  L03_SIG1 w3.6: v1(932.72,1746.47) 946.12,1759.87 946.12,1843.46 961.25,1858.59 976.98,1858.59 979.64,1855.92 1065.27,1855.92 1070.43,1850.76 1131.71,1850.76 1170.31,1889.37 1273.07,1889.37 1332.22,1830.22 1452.9,1830.22 1478.7,1804.41 1601.22,1804.41 1774.3,1631.32 1820.3,1631.32 1922.04,1529.58 1922.04,1373.39 1907.87,1359.22 1907.87,1274.34 1969.59,1212.62 1969.59,1178.96 1969.53,1178.9 1969.53,1104.08 1969.53,1029.26 1861.48,921.21 1861.48,898.04 1874.85,884.67 1874.85,689.4 1800.14,614.68 1800.14,492.11 1837.78,454.47 1837.78,334.96 1803.68,300.86 1727.98,300.86 1705.74,278.62 1705.74,242.83 1778.68,169.89 1778.68,147.59 1775.14,144.04 v1(1775.14,117.85)
  Bottom Layer w5.8: v1(1775.14,117.85) 1775.14,121.15 1778.96,124.96 J1.31@1778.96,182.59
AM26x_UART2_RXD: J2.26 R212.1 | length 1384.8
  Top Layer w5.8: R212.1@963.78,1672.83 963.78,1691.29 968.22,1695.73 973.09,1695.73 v1(975.43,1698.07)
  L08_SIG2 w3.6: v1(108.41,1659.96) 82.86,1685.51 82.86,1833.47 94.44,1845.06 241.62,1845.06 247.19,1850.63 373.09,1850.63 490.85,1732.87 623.09,1732.87 658.37,1697.58 711.26,1697.58 740.31,1726.63 884.96,1726.63 913.53,1698.07 927.94,1698.07 v1(975.43,1698.07)
  Bottom Layer w5.8: v1(108.41,1659.96) 108.07,1659.62 108.07,1627.43 102.4,1621.76 102.4,1592.19 141.59,1553.01 J2.26@196.81,1553.01
AM26x_UART2_TXD: J2.28 U1.A8 | length 1572.1
  Top Layer w5.8: U1.A8@1009.64,1564.41 1009.64,1598.12 1014.98,1603.47 1014.98,1653.32 1009.72,1658.58 1009.72,1680.15 v1(1009.98,1680.41)
  L08_SIG2 w3.6: v1(130.02,1684.99) 112.25,1684.99 93.66,1703.58 93.66,1822.14 105.77,1834.26 246.1,1834.26 251.66,1839.83 368.62,1839.83 486.38,1722.06 620.32,1722.06 694.07,1648.3 752.97,1648.3 766.93,1634.34 810.78,1634.34 841.51,1665.07 842.41,1665.07 846.37,1669.02 916.13,1669.02 927.51,1680.41 v1(1009.98,1680.41)
  Bottom Layer w5.8: v1(130.02,1684.99) 101.74,1684.99 89.4,1672.66 89.4,1586.81 142.89,1533.33 J2.28@196.81,1533.33
AM26x_USB0_DM: J2.40 R165.1 | length 1567
  Top Layer w4.2: v1(695.62,778.72) 707.16,790.27 716.09,790.27 723.59,797.76 723.59,814.29 709.14,828.74 709.14,847.85 711.6,850.31 713.12,850.31 R165.1@720.37,857.56
  L08_SIG2 w3.7: v1(123.26,1409.22) 134.25,1420.21 153,1420.21 161,1412.21 161,1388.33 141.08,1368.4 113.87,1368.4 90.11,1344.64 75.73,1344.64 45.3,1314.21 45.3,889.35 112.85,821.8 302.27,821.8 331.01,850.54 386.89,850.54 437.87,799.56 490.16,799.56 527.03,799.56 549.36,821.88 607.38,821.88 644.12,821.88 676.29,789.72 684.63,789.72 v1(695.62,778.72)
  Bottom Layer w4.2: v1(123.26,1409.22) 124.46,1409.22 136,1420.76 147.58,1420.76 149.73,1418.62 193.41,1418.62 J2.40@196.81,1415.22
AM26x_USB0_DP: J2.38 R168.1 | length 1602.4
  Top Layer w4.2: R168.1@689.31,857.56 696.56,850.31 698.08,850.31 700.54,847.85 700.54,825.18 714.99,810.72 714.99,801.33 712.53,798.87 707.16,798.87 v1(695.62,810.41)
  L08_SIG2 w3.7: v1(123.26,1440.9) 134.25,1429.91 157.02,1429.91 170.7,1416.23 170.7,1384.31 145.09,1358.7 117.89,1358.7 94.12,1334.94 79.75,1334.94 55,1310.19 55,893.37 116.87,831.5 298.25,831.5 326.99,860.24 390.91,860.24 441.89,809.26 461.02,809.26 463.36,811.6 463.36,814.92 465.7,817.26 472.72,817.26 475.06,814.92 475.06,811.6 477.4,809.26 484.42,809.26 486.76,811.6 486.76,814.92 489.1,817.26 496.12,817.26 498.46,814.92 498.46,811.6 500.8,809.26 523.02,809.26 545.34,831.58 594.85,831.58 597.19,833.92 597.19,839.13 599.53,841.47 606.55,841.47 608.89,839.13 608.89,833.92 611.23,831.58 618.25,831.58 620.59,833.92 620.59,839.13 622.93,841.47 629.95,841.47 632.29,839.13 632.29,833.92 634.63,831.58 648.14,831.58 680.3,799.42 684.63,799.42 v1(695.62,810.41)
  Bottom Layer w4.2: v1(123.26,1440.9) 124.46,1440.9 136,1429.36 147.58,1429.36 149.73,1431.5 193.41,1431.5 J2.38@196.81,1434.9
AM26x_VREFHI1: J1.85 S1.3 | length 473.7
  Top Layer w10: S1.3@964.43,567.43 964.61,567.61 v1(1008.98,567.61)
  L06_PWR2 w20: v1(1008.98,567.61) 1009.24,567.35 1009.24,455.55 1082.92,381.86 1082.92,290.97 1063.7,271.74 v1(1063.7,268.34)
  Bottom Layer w10: J1.85@1050.49,182.59 1050.49,255.14 v1(1063.7,268.34)
AM26x_VREFHI2: J1.83 S1.6 | length 568.8
  Top Layer w10: S1.6@1110.09,567.43 1110.41,567.11 v1(1152.23,567.11)
  L06_PWR2 w20: v1(1103.69,255.17) 1125.59,277.07 1125.59,395.76 1051.5,469.86 1051.5,523.73 1094.87,567.11 v1(1152.23,567.11)
  Bottom Layer w10: J1.83@1070.18,182.59 1070.18,243.88 1079.93,253.64 1102.16,253.64 v1(1103.69,255.17)
AM26x_VREFLO: C123.1 C124.1 C125.1 C126.1 C127.1 C128.1 J1.87 R75.2 R78.2 U1.V11 U1.V13 | length 2090.4
  Top Layer w8: C127.1@1066.4,949.25 1090.11,949.25 1104.35,935 1132,935 ; U1.V11@1104.27,1028.97 1122.39,1010.86 1135.71,1010.86 1145.96,1000.61 1162.25,1000.61 1167.12,1005.47 U1.V13@1167.12,1028.97 ; C126.1@1140.6,910.2 1140.6,926.4 1132,935 ; v1(1144.25,1001.08) 1144.25,998.9 1129.18,983.83 C128.1@1129.18,965.15 1129.95,964.38 1129.95,937.05 1132,935
  Top Layer w10: v1(1008.75,846.14) 1009.52,846.92 1030.81,846.92 R75.2@1031.59,847.7
  L05_PWR1 w10: v1(1030.64,257.59) 1005.44,282.79 835.55,282.79 564.92,553.43 564.92,675.55 612.94,723.57 746.71,723.57 869.27,846.14 v1(1008.75,846.14) 1032.32,869.71 1032.32,962.4 1057.26,987.34 1087.86,1017.94 1127.63,1017.94 1144.25,1001.32 v1(1144.25,1001.08)
  Bottom Layer w5.8: v1(1030.64,257.59) 1030.64,238.87 1030.73,238.79 1030.73,182.67 J1.87@1030.81,182.59
  Bottom Layer w10: v1(1144.25,1001.08) 1144.25,1000.16 1152.22,992.19 C124.1@1152.22,978.34 C125.1@1152.22,942.32 1191.02,942.32 1199.05,934.28 R78.2@1243.22,934.28 ; C123.1@1214.24,889.41 1236.42,889.41 1242.98,895.97 R78.2@1242.98,933.55
BOOST_COMP: C102.2 R192.2 U22.4 | length 120.1
  Top Layer w10: U22.4@2782.71,491.98 2800.09,491.98 2806.13,498.02 2806.13,514.67 2810.95,519.48 R192.2@2841.66,519.48 C102.2@2841.66,559.48
BOOST_EN: R45.2 R188.2 U22.7 | length 121.7
  Top Layer w10: R45.2@2629.27,562.84 2629.02,562.59 2629.02,528.08 R188.2@2628.78,527.84 2652.07,527.84 2659.58,520.33 2659.58,502.83 2670.42,491.98 U22.7@2690.19,491.98
BOOST_FB: R190.1 R209.2 U22.3 | length 149.7
  Top Layer w10: U22.3@2782.71,472.3 v1(2816.35,472.3) R209.2@2841.94,472.3
  Bottom Layer w5.8: R190.1@2756.8,511.89 2756.8,487.06 2771.56,472.3 v1(2816.35,472.3)
BOOST_FSW: R34.1 U22.1 | length 18.6
  Top Layer w5.8: U22.1@2782.71,432.93 2788.61,432.93 2797.59,423.95
BOOST_ILIM: R194.2 U22.8 | length 64.7
  Top Layer w5.8: R194.2@2631.61,487.06 2652.42,487.06 2667.18,472.3 U22.8@2690.19,472.3
BOOST_SW: C61.1 L3.2 R34.2 U22.11
  other v2: 2736.45,423.08
BUCK_FB: R30.1 R32.2 U3.9 | length 144.2
  Top Layer w12: R32.2@1583.2,1937.28 R30.1@1583.2,1884.88 1624.55,1884.88 1639.76,1869.67 U3.9@1639.76,1840.76
BUCK_SS: C132.1 U3.8 | length 50
  Top Layer w5.8: U3.8@1659.81,1845.56 C132.1@1659.81,1895.56
CLOCK_VDD: C115.1 C116.1 FB3.2 U5.6 | length 140.6
  Top Layer w15: FB3.2@82.8,536.53 C116.1@82.8,500.97 C115.1@127.8,500.97 U5.6@187.8,500.97
COMP1_OUT: TP5.1 U2.23 | length 83.9
  Top Layer w5.8: U2.23@2250.76,976.62 2250.76,940.64 2256.05,935.35 TP5.1@2296.51,935.35
COMP2_OUT: TP2.1 U2.26 | length 49.8
  Top Layer w5.8: TP2.1@2250.34,1321.58 2250.53,1321.4 2250.53,1272.13 U2.26@2250.71,1271.95
DAC_SPI3_CLK: J7.13 U18.3 | length 2671.5
  Top Layer w5.8: v1(1464.86,416.52) 1466.47,414.91 J7.13@1466.47,331.06
  L03_SIG1 w3.6: v1@1046.4,1778.75 1049.57,1778.75 1064.55,1763.77 1070.01,1763.77 1131.11,1702.66 1324.55,1702.66 1342.47,1684.75 1596.09,1684.75 1668.44,1612.4 1668.44,1486.33 1687,1467.77 1687,1416.45 1661.92,1391.37 1661.92,1378.31 1640.44,1356.84 1640.44,818.83 1658.55,800.72 1658.55,703.31 1612.06,656.82 1612.06,605.16 1563.68,556.78 1563.68,503.2 1548.7,488.22 1548.7,454.15 1511.05,416.5 v1(1464.86,416.52)
  Bottom Layer w5.8: U18.3@1017.3,2249.84 1049.13,2249.84 1067.46,2231.5 1067.46,2112.82 1038.75,2084.11 1038.75,1981.95 1068.68,1952.02 1068.68,1897.72 1048.7,1877.74 1048.7,1839.8 1064.12,1824.37 1064.12,1796.64 v1(1046.32,1778.83)
DAC_SPI3_CS0: J7.16 U18.13 | length 2784
  Top Layer w5.8: J7.16@1366.47,136.18 1367.31,137.02 v1(1367.31,221.62)
  L03_SIG1 w3.6: v1(1350.05,1722.28) 1363.56,1708.77 1599.22,1708.77 1688.78,1619.21 1688.78,1493.14 1706.2,1475.72 1706.2,1313.77 1684.54,1292.12 1684.54,699.37 1631.26,646.09 1631.26,545.99 1595.69,510.41 1595.69,422.62 1543.49,370.43 1508.79,370.43 1495.74,357.38 1495.74,316.52 1449.57,270.35 1449.57,215.75 1430.01,196.19 1392.74,196.19 v1(1367.31,221.62)
  Bottom Layer w5.8: U18.13@1241.71,2275.43 1202.23,2275.43 1172.37,2245.57 1172.37,2092.35 1304.72,1960.01 1304.72,1767.61 v1(1350.05,1722.28)
DAC_SPI3_D0: J7.14 U18.6 | length 3288.5
  Top Layer w5.8: v1(1436.93,51.63) 1459.75,51.63 1466.47,58.35 J7.14@1466.47,136.18
  L03_SIG1 w3.6: v1(1101.19,1756.35) 1101.51,1756.35 1114.2,1769.03 1117.29,1769.03 1128.08,1779.82 1152.67,1779.82 1176.75,1803.9 1281.53,1803.9 1329.34,1756.09 1580.8,1756.09 1701.38,1635.5 1701.38,1536.26 1726.62,1511.02 1726.62,1261.4 1704.38,1239.16 1704.38,807.98 1725.24,787.12 1725.24,755.48 1697.01,727.26 1697.01,684.41 1640.86,628.26 1640.86,542.01 1605.86,507.01 1605.86,411.62 1459.17,264.93 1459.17,152.17 1403,96 1403,63 1414.37,51.63 v1(1436.93,51.63)
  Bottom Layer w5.8: U18.6@1017.3,2326.61 1065.76,2326.61 1103.76,2288.61 1103.76,2099.25 1064.75,2060.23 1064.75,2016.62 1148.04,1933.33 1148.04,1832.6 1128.23,1812.79 1128.23,1764.22 1120.35,1756.35 v1(1101.19,1756.35)
DAC_SPI3_D1: J7.15 U18.10 | length 3263.4
  Top Layer w5.8: J7.15@1366.47,331.06 1366.47,247.78 1379.02,235.23 1396.38,235.23 v1(1397.08,234.53)
  L03_SIG1 w3.6: v1(1050.39,1754.17) 1066.03,1754.17 1099.28,1720.92 1099.28,1664.23 1099.15,1664.1 1099.15,1632.31 1101.82,1629.65 1117.73,1613.74 1172.75,1613.74 1188.66,1629.65 1252.08,1693.06 1320.58,1693.06 1339.23,1674.41 1592.84,1674.41 1658.84,1608.42 1658.84,1502.38 1650.27,1493.82 1650.27,1381.94 1630.84,1362.51 1630.84,814.86 1646.61,799.09 1648.95,796.75 1648.95,707.29 1646.61,704.95 1600.88,659.21 1600.88,608.3 1554.08,561.5 1554.08,542.57 1448.06,436.55 1448.06,306.92 1397.08,255.94 v1(1397.08,234.53)
  Bottom Layer w5.8: v1(1050.39,1754.17) 1075.84,1754.17 1092.08,1737.92 1128.14,1737.92 1140.03,1749.81 1140.03,1796.44 1190.17,1846.57 1190.17,1947.01 1131.21,2005.97 1131.21,2341.34 1149.62,2359.75 1183.1,2359.75 1191.6,2351.26 1240.77,2351.26 U18.10@1241.71,2352.2
DAC_TCK: J1.22 J7.4 R314.1 | length 3665.1
  Top Layer w5.8: v1(1910.08,267.16) 1912.42,264.82 1920.71,264.82 1966.47,219.06 J7.4@1966.47,136.18
  L03_SIG1 w3.6: v1(1879.62,527) 1879.62,297.62 v1(1910.08,267.16)
  L08_SIG2 w3.6: v1(1879.62,527) 1863.72,511.1 1863.72,448.35 1925.66,386.41 2129.83,386.41 2161.97,354.26 2246.31,354.26 2292.97,400.93 2538.8,400.93 2589.37,451.5 2664.98,451.5 2716.17,400.31 2937.3,400.31 v1(2963.32,426.33)
  Bottom Layer w5.8: J1.22@1877.38,408.19 1877.38,480.53 1869.2,488.71 1869.2,501 1879.62,511.42 v1(1879.62,527) ; R314.1@2738.4,1972.55 2814.6,1972.55 2991.06,1796.09 2991.06,1635.79 3048.39,1578.47 3048.39,1198.71 3004.66,1154.99 3004.66,1008.81 3072.71,940.76 3072.71,535.72 v1(2963.32,426.33)
DAC_TDI: J1.19 J7.5 R316.1 | length 3481.7
  Top Layer w5.8: v1(1858.65,243.59) 1858.65,244.81 1866.47,252.62 J7.5@1866.47,331.06
  L03_SIG1 w3.6: v1(1858.65,243.59) 1858.65,139.94 v1(1907.47,91.13)
  Bottom Layer w5.8: J1.19@1897.07,182.59 1897.07,100.63 1906.56,91.13 v1(1907.47,91.13) 1924.05,74.55 2217.55,74.55 2261.69,118.69 2464.54,118.69 2505.84,77.4 2894.84,77.4 2945.42,127.97 2945.42,485.96 3060.91,601.45 3060.91,935.87 2991.66,1005.12 2991.66,1162.79 3035.39,1206.52 3035.39,1573.08 2877.73,1730.74 2877.73,1843.65 2803.92,1917.46 R316.1@2763.02,1917.46
DAC_TDO: J1.21 J7.6 R315.1 | length 2915.2
  Top Layer w5.8: J7.6@1866.47,136.18 1866.47,54.66 1871.21,49.92 1915.33,49.92 1928.47,63.05 1928.47,100.25 1918.41,110.31 v1(1918.41,113.61) ; R315.1@2920.33,1794.32 2920.33,1779.99 2931.28,1769.04 v1(2931.28,1768.61)
  L03_SIG1 w3.6: v1(1895.29,243.59) 1895.29,136.73 1966.25,65.77 2312.4,65.77 2451.59,204.96 2451.59,632.32 2586.72,767.45 2707.16,767.45 2734.24,794.54 2767.14,794.54 2879.37,906.78 2879.37,1510.21 2895.22,1526.06 2895.22,1612.22 2916.01,1633.01 2916.01,1753.34 v1(2931.28,1768.61)
  Bottom Layer w5.8: J1.21@1877.38,182.59 1877.38,240.19 1880.78,243.59 v1(1895.29,243.59)
DAC_TMS: J1.24 J7.3 R313.1 | length 3147.6
  Top Layer w5.8: v1(1910.91,327.57) 1910.91,409.04 1925.68,423.81 1956.26,423.81 1966.47,413.61 J7.3@1966.47,331.06 ; R313.1@2793.89,1804.15 2793.89,1819.8 2800.64,1826.56 v1(2859.83,1826.56)
  L03_SIG1 w3.6: v1(1910.91,327.57) 1936.77,301.71 1936.77,124.34 1985.74,75.37 2308.42,75.37 2441.99,208.93 2441.99,636.3 2583.21,777.53 2703.65,777.53 2730.27,804.14 2763.16,804.14 2869.5,910.48 2869.5,1619.5 2825.79,1663.21 2825.79,1755.79 2859.83,1789.83 v1(2859.83,1826.56)
  Bottom Layer w5.8: J1.24@1857.7,408.19 1857.7,348.1 1878.22,327.57 v1(1910.91,327.57)
DAC_VREF: C153.2 C154.2 R310.1 S2.2 U1.T13 | length 1542.2
  Top Layer w10: U1.T13@1167.12,1091.97 v1(1182.86,1076.22) ; v1(1556.57,1027.96) 1556.57,921.86 1601.43,876.99 1601.43,833.46 1626.09,808.81 1626.09,773.56 1579.52,727 S2.2@1579.52,686.66
  L06_PWR2 w15: v1(830.38,927.38) 861.45,927.38 970.55,818.29 1122.73,818.29 1175.76,871.32 1319.93,871.32 1349.11,900.5 1406.48,900.5 1424.75,882.23 1482.12,882.23 1556.57,956.68 v1(1556.57,1027.96)
  Bottom Layer w6: v1@1181.56,1076.9 1198.41,1060.04 1198.41,1030.95 1188.84,1021.38 C154.2@1188.84,1004.41
  Bottom Layer w10: v1(830.38,927.38) 879.32,927.38 890.54,938.61 C153.2@890.54,956.98 ; C153.2@890.33,957.18 890.33,974.18 902.53,986.38 R310.1@902.53,1000.92
EXT_VMON1: R29.1 R33.2 U2.16 | length 1952.9
  Top Layer w5.8: R29.1@1684.64,1635.21 R33.2@1744.64,1635.21 1744.64,1617.89 1757.62,1604.92 1776.25,1604.92 1798.99,1582.18 1798.99,1491.91 1778.9,1471.82 1778.9,1452.89 1790.47,1441.32 1789.74,1440.59 1789.74,1431.09 v1(1787.41,1428.76) ; U2.16@2112.91,976.67 2112.91,935.97 2131.81,917.07 v1(2131.81,902.58)
  L03_SIG1 w3.6: v1(1762.57,750.34) 1762.57,816.93 1733.18,846.33 1733.18,1227.23 1781.26,1275.31 1781.26,1375.35 1787.41,1381.5 v1(1787.41,1428.76)
  L08_SIG2 w3.6: v1(1762.57,750.34) 1761.94,749.71 1707.11,749.71 1690.43,766.39 1690.43,790.92 1696.04,796.52 1700.23,800.71 1700.23,931.23 1732,963 1956,963 1977.51,941.49 1977.51,926.7 1974.21,923.4 1974.21,892.29 1979.74,886.75 1995.05,886.75 2007.96,899.66 2007.96,930.66 2037.46,960.16 2096.87,960.16 2131.81,925.22 v1(2131.81,902.58)
EXT_VMON2: J3.59 U2.10 | length 692.5
  Top Layer w5.8: v1(1991.01,916.69) 1991.16,916.85 1991.16,935.6 1994.8,939.24 U2.10@1994.8,976.67
  L08_SIG2 w3.6: v1(1991.01,916.69) 1991.01,929.51 2031.26,969.76 2101.29,969.76 2137.03,934.02 v1(2431.23,934.02)
  Bottom Layer w5.8: J3.59@2362.59,1001.63 2362.92,1001.31 2432.13,1001.31 2443.11,990.33 2443.11,945.9 v1(2431.23,934.02)
EXT_VREF1: S1.2 U11.3 | length 759.3
  Top Layer w10: v1(908.73,641.65) 910.9,641.65 913.85,638.69 962.05,638.69 S1.2@964.43,636.32
  L06_PWR2 w12: v1(908.73,641.65) 937.87,670.78 1062.97,670.78 1102.96,630.79 1157.12,630.79 1207.27,580.64 1207.27,580.33 1262.47,525.13 1339.32,525.13 1356.38,542.2 1449.38,542.2 v1(1450.13,542.95)
  Bottom Layer w10: U11.3@1406.88,585.18 1440.86,585.18 1450.13,575.92 v1(1450.13,542.95)
EXT_VREF1_SW: S4.3 U11.1 U11.2 | length 359.5
  Top Layer w10: S4.3@1205.84,567.43 1251.88,567.43 1259.1,560.2 v1(1260.25,560.2)
  Bottom Layer w5.8: v1@1260.27,560.18 v1@1261.81,560.18
  Bottom Layer w10: U11.1@1406.88,535.18 1286.81,535.18 1261.81,560.18 1289.37,560.18 U11.2@1406.88,560.18
EXT_VREF2: S1.5 U11.5 U11.14 | length 930.3
  Top Layer w10: S1.5@1110.09,636.32 1147.66,636.32 1156.94,645.6 v1(1156.94,665.79)
  L06_PWR2 w15: v1(1156.94,665.79) 1186.08,665.79 1244.33,607.54 1272.94,607.54 1297.75,632.35 1367.12,632.35 1413.37,586.1 1529.48,586.1 1547.63,604.24 v1(1548.44,604.24)
  Bottom Layer w10: v1(1156.94,665.79) 1156.94,632.31 1206.73,582.52 1318.88,582.52 1371.55,635.18 U11.5@1406.88,635.18 ; v1(1548.44,604.24) 1548.44,604.05 1567.3,585.18 U11.14@1621.45,585.18
EXT_VREF2_SW: S4.6 U11.6 U11.7 | length 297.6
  Top Layer w10: v1(1302.5,604.48) 1302.5,586.87 1302.41,586.78 1302.41,574.61 1309.78,567.24 S4.6@1351.32,567.24
  Bottom Layer w10: v1(1302.5,604.48) 1336.47,638.45 1336.47,661.99 1348.47,673.99 ; U11.6@1406.88,660.18 1362.27,660.18 1348.47,673.99 ; U11.7@1406.88,685.18 1359.66,685.18 1348.47,673.99
FET_CT: C83.2 U14.6 | length 90.7
  Top Layer w5.8: U14.6@2414.76,221.34 2429.09,221.34 2468.84,181.59 C83.2@2468.84,161.4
